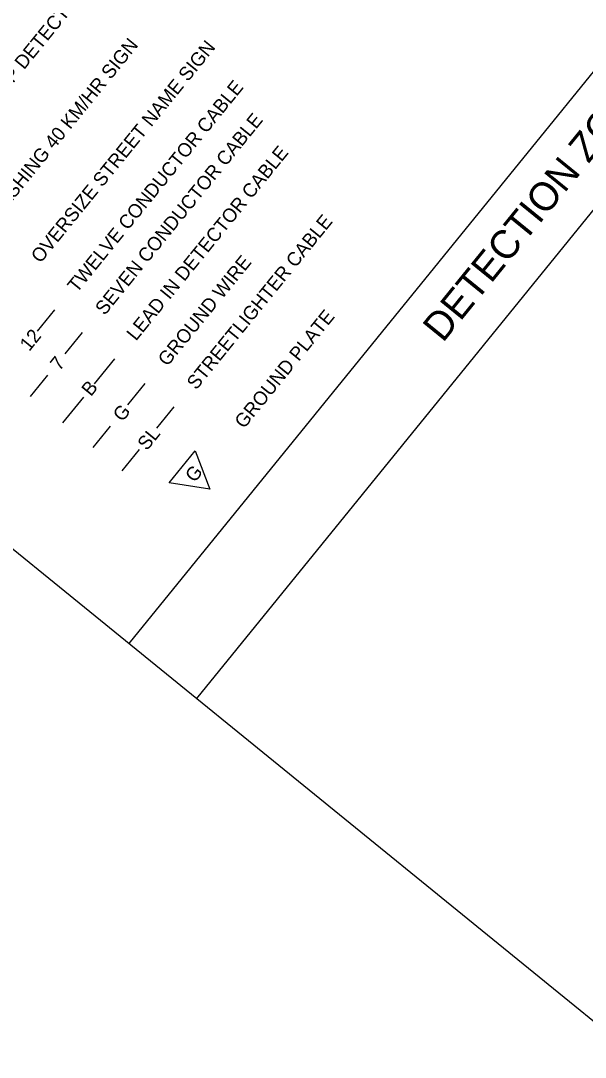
# Model space of a CAD drawing. Extents: x 592613 to 600223, y 4837996 to 4840103.
# Drawn here: x 592933.8 to 592951.62, y 4839229.51 to 4839262.21 of the extents above; entities that cross this region are included whole.
import ezdxf

# ---------------------------------------------------------------- set-up
doc = ezdxf.new("R2010")
doc.units = 0
for name, color, linetype in [('ENG_BORDER', 7, 'Continuous'), ('ENG_TITLEBLOCK', 7, 'Continuous'), ('ENG_TX_TITLEBLOCK', 7, 'Continuous'), ('TCS_LEGEND', 7, 'Continuous'), ('TCS_PLATE', 7, 'Continuous'), ('TCS_WR_12', 7, 'Continuous'), ('TCS_WR_7', 7, 'Continuous'), ('TCS_WR_B', 7, 'Continuous'), ('TCS_WR_G', 7, 'Continuous'), ('TCS_WR_SL', 7, 'Continuous')]:
    doc.layers.add(name, color=color, linetype=linetype)

msp = doc.modelspace()

# ---------------------------------------------------------------- linework, layer by layer
at = {"layer": 'ENG_BORDER'}
msp.add_lwpolyline([(592902.303, 4839270.934), (593006.685, 4839186.123)], dxfattribs=at)
at = {"layer": 'ENG_TITLEBLOCK'}
msp.add_line((592939.353, 4839240.83), (592966.893, 4839274.724), dxfattribs=at)
msp.add_line((592939.353, 4839240.83), (592966.893, 4839274.724), dxfattribs=at)
msp.add_lwpolyline([(592937.219, 4839242.565), (592964.758, 4839276.458)], dxfattribs=at)
msp.add_lwpolyline([(592937.219, 4839242.565), (592964.758, 4839276.458)], dxfattribs=at)
at = {"layer": 'TCS_PLATE'}
for p, q in [((592938.485, 4839247.637), (592939.305, 4839248.646)), ((592939.305, 4839248.646), (592939.77, 4839247.431)), ((592939.77, 4839247.431), (592938.485, 4839247.637))]:
    msp.add_line(p, q, dxfattribs=at)
at = {"layer": 'TCS_WR_12'}
msp.add_line((592934.321, 4839252.417), (592934.868, 4839253.09), dxfattribs=at)
at = {"layer": 'TCS_WR_7'}
for p, q in [((592935.2, 4839251.703), (592935.747, 4839252.376)), ((592934.106, 4839250.356), (592934.653, 4839251.029))]:
    msp.add_line(p, q, dxfattribs=at)
at = {"layer": 'TCS_WR_B'}
for p, q in [((592936.129, 4839250.753), (592936.771, 4839251.544)), ((592935.13, 4839249.524), (592935.785, 4839250.33))]:
    msp.add_line(p, q, dxfattribs=at)
at = {"layer": 'TCS_WR_G'}
for p, q in [((592937.18, 4839250.094), (592937.727, 4839250.767)), ((592936.086, 4839248.747), (592936.633, 4839249.421))]:
    msp.add_line(p, q, dxfattribs=at)
at = {"layer": 'TCS_WR_SL'}
for p, q in [((592938.092, 4839249.353), (592938.639, 4839250.026)), ((592936.998, 4839248.007), (592937.545, 4839248.68))]:
    msp.add_line(p, q, dxfattribs=at)

# ---------------------------------------------------------------- texts
at = {"layer": 'ENG_TX_TITLEBLOCK'}
msp.add_text('DETECTION ZONE - PLAN VIEW', height=0.9, rotation=50.9062, dxfattribs=at).set_placement((592947.124, 4839252.03))
at = {"layer": 'TCS_LEGEND'}
for s, p in [('VEHICLE LOOP DETECTOR', (592931.117, 4839257.22)), ('FLASHING 40 KM/HR SIGN', (592932.917, 4839255.758)), ('OVERSIZE STREET NAME SIGN', (592934.419, 4839254.538)), ('TWELVE CONDUCTOR CABLE', (592935.57, 4839253.603)), ('SEVEN CONDUCTOR CABLE', (592936.445, 4839252.892)), ('LEAD IN DETECTOR CABLE', (592937.435, 4839252.087)), ('STREETLIGHTER CABLE', (592939.337, 4839250.542)), ('GROUND WIRE', (592938.425, 4839251.283)), ('GROUND PLATE', (592940.845, 4839249.317))]:
    msp.add_text(s, height=0.43374, rotation=50.9061, dxfattribs=at).set_placement(p)
at = {"layer": 'TCS_PLATE'}
msp.add_text('G', height=0.434, rotation=50.9061, dxfattribs=at).set_placement((592939.286, 4839247.617))
at = {"layer": 'TCS_WR_12'}
msp.add_text('12', height=0.4337, rotation=50.9061, dxfattribs=at).set_placement((592934.065, 4839251.758))
at = {"layer": 'TCS_WR_7'}
msp.add_text('7', height=0.434, rotation=50.9061, dxfattribs=at).set_placement((592935.024, 4839251.143))
at = {"layer": 'TCS_WR_B'}
msp.add_text('B', height=0.434, rotation=50.9061, dxfattribs=at).set_placement((592936.013, 4839250.336))
at = {"layer": 'TCS_WR_G'}
msp.add_text('G', height=0.434, rotation=50.9061, dxfattribs=at).set_placement((592937.005, 4839249.534))
at = {"layer": 'TCS_WR_SL'}
msp.add_text('SL', height=0.4337, rotation=50.9061, dxfattribs=at).set_placement((592937.779, 4839248.625))

doc.saveas('drawing.dxf')
